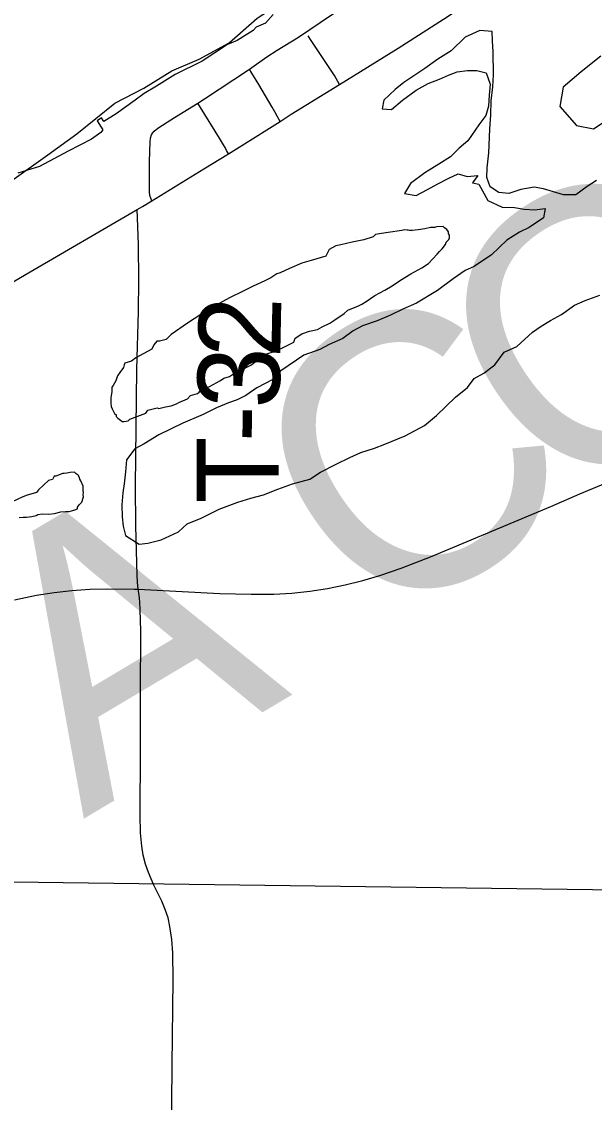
# Model space of a CAD drawing. Extents: x 63.4 to 97.4, y 0.4 to 22.4.
# Drawn here: x 66.101 to 66.497, y 16.424 to 17.173 of the extents above; entities that cross this region are included whole.
import ezdxf

# ---------------------------------------------------------------- set-up
doc = ezdxf.new("R2010")
doc.units = 0
for name, color, linetype in [('GM_X_County_Road', 7, 'Continuous'), ('GM_X_County_Text', 7, 'Continuous'), ('GM_X_Major_Lake', 7, 'Continuous'), ('GM_X_Minor_River', 7, 'Continuous'), ('GM_X_Section', 7, 'Continuous'), ('GM_X_State_Route', 7, 'Continuous'), ('GM_X_Township_Road', 7, 'Continuous'), ('GM_X_Township_Road_Text', 7, 'Continuous'), ('SH_Cut_Line', 7, 'Continuous')]:
    doc.layers.add(name, color=color, linetype=linetype)

msp = doc.modelspace()

# ---------------------------------------------------------------- linework, layer by layer
at = {"layer": 'GM_X_County_Road'}
msp.add_lwpolyline([(66.27518, 17.17769), (66.26982, 17.17168), (66.26348, 17.16907), (66.2612, 17.16664), (66.25015, 17.15981), (66.24348, 17.15688), (66.22593, 17.1455), (66.2074, 17.13624), (66.1944, 17.12811), (66.18595, 17.12307), (66.17961, 17.11852), (66.16644, 17.10893), (66.158, 17.10375), (66.15634, 17.10613), (66.15344, 17.10406), (66.15718, 17.09788), (66.15588, 17.09593), (66.14937, 17.09138), (66.13328, 17.08309), (66.11345, 17.07252), (66.09849, 17.06781)], dxfattribs=at)
at = {"layer": 'GM_X_Major_Lake'}
for points in [[(66.11926, 17.08066), (66.13935, 17.0951), (66.16551, 17.11638), (66.18561, 17.12664), (66.20495, 17.1388), (66.22391, 17.14677), (66.24476, 17.15817), (66.2641, 17.17527), (66.28306, 17.18743), (66.30163, 17.20642), (66.32097, 17.21972), (66.34182, 17.23834), (66.36268, 17.24935), (66.38429, 17.26265), (66.40325, 17.27937), (66.42524, 17.29419), (66.44685, 17.30786), (66.46619, 17.32192), (66.48515, 17.33674), (66.50638, 17.35497)], [(66.09423, 17.06281), (66.11926, 17.08066)]]:
    msp.add_lwpolyline(points, dxfattribs=at)
at = {"layer": 'GM_X_Minor_River'}
for points in [[(66.49891, 17.0629), (66.49248, 17.05869), (66.48454, 17.05295), (66.47618, 17.05291), (66.46212, 17.05703), (66.45566, 17.05814), (66.44655, 17.05658), (66.43821, 17.05387), (66.43137, 17.0546), (66.42528, 17.05838), (66.42297, 17.06483), (66.42331, 17.07167), (66.4244, 17.08194), (66.42508, 17.09829), (66.42579, 17.10817), (66.42612, 17.11805), (66.42721, 17.12756), (66.42754, 17.13593), (66.42746, 17.15189), (66.42704, 17.15949), (66.42663, 17.16595), (66.41827, 17.16667), (66.40805, 17.16206), (66.39822, 17.15251), (66.38914, 17.14677), (66.38006, 17.14026), (66.36568, 17.1307), (66.35963, 17.12573), (66.3517, 17.11847), (66.35059, 17.11238), (66.35705, 17.11203), (66.36461, 17.11853), (66.37406, 17.12541), (66.38239, 17.13001), (66.39035, 17.13309), (66.39641, 17.13578), (66.40247, 17.13809), (66.40968, 17.13888), (66.41614, 17.13891), (66.4226, 17.13742), (66.4253, 17.12945), (66.42459, 17.12187), (66.42424, 17.11424), (66.42237, 17.10777), (66.41747, 17.10129), (66.40993, 17.09023), (66.40388, 17.08526), (66.39784, 17.07915), (66.38989, 17.07418), (66.38005, 17.06805), (66.37022, 17.06078), (66.36607, 17.05392), (66.37406, 17.05244), (66.38201, 17.05665), (66.3892, 17.06049), (66.39677, 17.06432), (66.40321, 17.0674), (66.4093, 17.06552), (66.41689, 17.06632), (66.413, 17.0611), (66.41745, 17.06028), (66.42381, 17.04887), (66.4337, 17.04435), (66.44206, 17.04401), (66.4489, 17.0429), (66.45611, 17.04256), (66.46332, 17.04335), (66.46222, 17.03688), (66.45238, 17.03037), (66.44556, 17.02692), (66.43686, 17.02156), (66.42628, 17.01125), (66.41417, 17.00321), (66.40811, 17.00052), (66.39979, 16.99478), (66.38882, 16.98675), (66.37443, 16.97794), (66.36496, 16.97371), (66.35625, 16.96949), (66.34716, 16.96565), (66.33693, 16.96218), (66.33049, 16.95873), (66.32331, 16.95337), (66.31383, 16.94915), (66.3074, 16.9457), (66.29641, 16.94185), (66.28051, 16.93113), (66.27485, 16.92502), (66.26387, 16.91927), (66.2563, 16.91391), (66.25024, 16.91084), (66.24418, 16.90892), (66.23584, 16.90546), (66.22676, 16.90085), (66.21274, 16.89471), (66.19607, 16.88665)], [(66.50189, 17.14882), (66.48828, 17.13811), (66.47581, 17.12741), (66.47359, 17.1141), (66.48505, 17.10085), (66.49683, 17.09862), (66.50819, 17.1059)], [(66.50189, 17.14882), (66.48828, 17.13811), (66.47581, 17.12741), (66.47359, 17.1141), (66.48505, 17.10085), (66.49683, 17.09862), (66.50819, 17.1059)], [(66.37143, 17.02819), (66.36609, 17.02861), (66.36418, 17.02825), (66.35468, 17.0268), (66.35011, 17.02608), (66.34745, 17.02571), (66.34593, 17.02535), (66.3444, 17.02384), (66.33793, 17.02161), (66.32994, 17.02015), (66.32195, 17.01831), (66.31852, 17.01758), (66.31395, 17.01495), (66.31163, 17.01041), (66.30136, 17.00745), (66.29488, 17.0056), (66.2865, 17.00187), (66.28002, 16.99888), (66.27774, 16.99814), (66.27354, 16.99551), (66.26934, 16.99326), (66.26134, 16.98953), (66.25448, 16.98616), (66.24495, 16.98167), (66.23579, 16.97643), (66.22511, 16.97005), (66.21595, 16.96404), (66.20449, 16.95616), (66.20105, 16.95276), (66.19648, 16.95166), (66.19459, 16.95167), (66.19266, 16.94903), (66.19112, 16.946), (66.18006, 16.94001), (66.17701, 16.93775), (66.17244, 16.93627), (66.17205, 16.93513), (66.17166, 16.93323), (66.16897, 16.92984), (66.16744, 16.92757), (66.16627, 16.92416), (66.16434, 16.92076), (66.16358, 16.91962), (66.16355, 16.91659), (66.16315, 16.91393), (66.16276, 16.91204), (66.16273, 16.90862), (66.1631, 16.90634), (66.16384, 16.90481), (66.16421, 16.90367), (66.16534, 16.90139), (66.16647, 16.90062), (66.16646, 16.89948), (66.16759, 16.89833), (66.16948, 16.8968), (66.17061, 16.89603), (66.17213, 16.89602), (66.17479, 16.89638), (66.17594, 16.89751), (66.18699, 16.9016), (66.18852, 16.90387), (66.19499, 16.90534), (66.19613, 16.90495), (66.2007, 16.90606), (66.2045, 16.90679), (66.20831, 16.90828), (66.20984, 16.90903), (66.21593, 16.91164), (66.21785, 16.9139), (66.2228, 16.91538), (66.22394, 16.91614), (66.22509, 16.91765), (66.23119, 16.92026), (66.23881, 16.92438), (66.24111, 16.92588), (66.24491, 16.92699), (66.24759, 16.92887), (66.25178, 16.93112), (66.25979, 16.93485), (66.26934, 16.94238), (66.27733, 16.94498), (66.28305, 16.94759), (66.28801, 16.95021), (66.28953, 16.95096), (66.29031, 16.95361), (66.29489, 16.95662), (66.30022, 16.95848), (66.30593, 16.95957), (66.30898, 16.96145), (66.31432, 16.96407), (66.31776, 16.96632), (66.32425, 16.97083), (66.32692, 16.97309), (66.33416, 16.97607), (66.33645, 16.97719), (66.3395, 16.97907), (66.34561, 16.9832), (66.35248, 16.98694), (66.35744, 16.98994), (66.36316, 16.9937), (66.37041, 16.9982)], [(66.37125, 17.02792), (66.36609, 17.02861), (66.36418, 17.02825), (66.35468, 17.0268), (66.35011, 17.02608), (66.34745, 17.02571), (66.34593, 17.02535), (66.3444, 17.02384), (66.33793, 17.02161), (66.32994, 17.02015), (66.32195, 17.01831), (66.31852, 17.01758), (66.31395, 17.01495), (66.31163, 17.01041), (66.30136, 17.00745), (66.29488, 17.0056), (66.2865, 17.00187), (66.28002, 16.99888), (66.27774, 16.99814), (66.27354, 16.99551), (66.26934, 16.99326), (66.26134, 16.98953), (66.25448, 16.98616), (66.24495, 16.98167), (66.23579, 16.97643), (66.22511, 16.97005), (66.21595, 16.96404), (66.20449, 16.95616), (66.20105, 16.95276), (66.19648, 16.95166), (66.19459, 16.95167), (66.19266, 16.94903), (66.19112, 16.946), (66.18006, 16.94001), (66.17701, 16.93775), (66.17244, 16.93627), (66.17205, 16.93513), (66.17166, 16.93323), (66.16897, 16.92984), (66.16744, 16.92757), (66.16627, 16.92416), (66.16434, 16.92076), (66.16358, 16.91962), (66.16355, 16.91659), (66.16315, 16.91393), (66.16276, 16.91204), (66.16273, 16.90862), (66.1631, 16.90634), (66.16384, 16.90481), (66.16421, 16.90367), (66.16534, 16.90139), (66.16647, 16.90062), (66.16646, 16.89948), (66.16759, 16.89833), (66.16948, 16.8968), (66.17061, 16.89603), (66.17213, 16.89602), (66.17479, 16.89638), (66.17594, 16.89751), (66.18699, 16.9016), (66.18852, 16.90387), (66.19499, 16.90534), (66.19613, 16.90495), (66.2007, 16.90606), (66.2045, 16.90679), (66.20831, 16.90828), (66.20984, 16.90903), (66.21593, 16.91164), (66.21785, 16.9139), (66.2228, 16.91538), (66.22394, 16.91614), (66.22509, 16.91765), (66.23119, 16.92026), (66.23881, 16.92438), (66.24111, 16.92588), (66.24491, 16.92699), (66.24759, 16.92887), (66.25178, 16.93112), (66.25979, 16.93485), (66.26934, 16.94238), (66.27733, 16.94498), (66.28305, 16.94759), (66.28801, 16.95021), (66.28953, 16.95096), (66.29031, 16.95361), (66.29489, 16.95662), (66.30022, 16.95848), (66.30593, 16.95957), (66.30898, 16.96145), (66.31432, 16.96407), (66.31776, 16.96632), (66.32425, 16.97083), (66.32692, 16.97309), (66.33416, 16.97607), (66.33645, 16.97719), (66.3395, 16.97907), (66.34561, 16.9832), (66.35248, 16.98694), (66.35744, 16.98994), (66.36316, 16.9937), (66.37041, 16.9982)], [(66.37041, 16.9982), (66.37804, 17.00232), (66.38262, 17.00533), (66.38875, 17.01173), (66.39028, 17.01362), (66.39219, 17.01551), (66.39449, 17.01853), (66.39489, 17.02004), (66.3968, 17.02193), (66.39719, 17.02306), (66.3972, 17.02496), (66.39645, 17.02611), (66.39646, 17.02725), (66.39533, 17.02877), (66.39382, 17.02992), (66.39269, 17.03107), (66.38813, 17.03073), (66.38699, 17.03036), (66.38395, 17.03038), (66.38014, 17.02927), (66.37558, 17.02854), (66.37143, 17.02819)], [(66.33262, 17.02348), (66.33262, 17.02355)], [(66.19607, 16.88665), (66.18585, 16.88052), (66.17942, 16.87706), (66.17376, 16.86944), (66.17304, 16.86107), (66.17195, 16.85271), (66.17122, 16.84662), (66.1705, 16.83825), (66.17055, 16.82989), (66.17134, 16.82344), (66.17289, 16.81698), (66.18241, 16.81094), (66.18848, 16.81173), (66.19758, 16.81405), (66.2097, 16.81943), (66.21575, 16.82516), (66.22522, 16.82901), (66.23772, 16.83515), (66.2506, 16.84015), (66.2597, 16.84285), (66.26842, 16.84517), (66.27827, 16.84902), (66.28851, 16.85287), (66.30064, 16.85597), (66.30783, 16.86094), (66.31881, 16.86631), (66.32828, 16.87092), (66.33586, 16.87437), (66.34533, 16.87746), (66.35253, 16.88016), (66.36655, 16.88592), (66.3798, 16.89321), (66.38812, 16.90009), (66.40134, 16.91269), (66.40966, 16.91957), (66.41419, 16.92567), (66.421, 16.92951), (66.42856, 16.93524), (66.43497, 16.94401), (66.44369, 16.94786), (66.45465, 16.95779), (66.4607, 16.962), (66.46713, 16.96583), (66.47471, 16.97005), (66.48379, 16.97655), (66.49098, 16.97962), (66.50122, 16.98347)], [(66.14029, 16.85866), (66.13877, 16.85981), (66.13764, 16.86096), (66.1346, 16.86061), (66.13232, 16.86024), (66.13042, 16.85988), (66.12928, 16.85989), (66.12661, 16.85877), (66.12471, 16.85802), (66.12357, 16.85803), (66.12241, 16.85576), (66.11975, 16.85502)], [(66.11975, 16.85502), (66.11286, 16.84862), (66.11133, 16.84673), (66.10752, 16.84562), (66.10486, 16.84488), (66.10181, 16.84376), (66.09419, 16.84002)], [(66.09942, 16.82935), (66.10209, 16.82971), (66.10436, 16.82969), (66.10816, 16.83005), (66.11121, 16.83078), (66.11235, 16.83153), (66.11577, 16.83189), (66.11995, 16.83186), (66.12375, 16.83221), (66.12832, 16.83331), (66.13136, 16.83367), (66.13402, 16.83365), (66.13554, 16.83402), (66.13783, 16.83476), (66.13973, 16.83551), (66.13974, 16.83665), (66.14089, 16.83816), (66.1428, 16.84004), (66.14397, 16.84383), (66.1436, 16.84535), (66.14399, 16.84687), (66.14362, 16.84801), (66.14365, 16.85105), (66.14216, 16.85485), (66.14141, 16.856), (66.14103, 16.85714), (66.14029, 16.85866)]]:
    msp.add_lwpolyline(points, dxfattribs=at)
at = {"layer": 'GM_X_Section'}
msp.add_lwpolyline([(66.68776, 16.56928), (66.716, 16.56874), (66.70719, 15.57748), (66.70364, 15.57723), (65.68816, 15.5852), (65.69377, 16.5825)], close=True, dxfattribs=at)
at = {"layer": 'GM_X_State_Route'}
msp.add_lwpolyline([(66.09617, 16.77234), (66.1113, 16.77566), (66.12353, 16.7776), (66.13585, 16.77897), (66.14821, 16.77985), (66.1606, 16.78013), (66.17922, 16.77982), (66.18182, 16.77973), (66.23821, 16.77694), (66.26, 16.77629), (66.27557, 16.77645), (66.28803, 16.77714), (66.30045, 16.77842), (66.31279, 16.78029), (66.32502, 16.78276), (66.33712, 16.7858), (66.34908, 16.78936), (66.36382, 16.79443), (66.38413, 16.80231), (66.46733, 16.83708), (66.48731, 16.84575), (66.5418, 16.86847)], dxfattribs=at)
at = {"layer": 'GM_X_Township_Road'}
for points in [[(66.25869, 17.13987), (66.27082, 17.14852), (66.2779, 17.15316), (66.29273, 17.16202), (66.31556, 17.17741), (66.33122, 17.18732), (66.35945, 17.20611), (66.37561, 17.21671)], [(66.32108, 17.12929), (66.3616, 17.15452), (66.39306, 17.17449), (66.39973, 17.17898)], [(66.32108, 17.12929), (66.31761, 17.13543), (66.30108, 17.16046), (66.29949, 17.16304)], [(66.22292, 17.11641), (66.22762, 17.11934), (66.25806, 17.13943), (66.25869, 17.13987)], [(66.27991, 17.10377), (66.27787, 17.10741), (66.27626, 17.11034), (66.2744, 17.11368), (66.26514, 17.12933), (66.26032, 17.1372), (66.25869, 17.13987)], [(66.27991, 17.10377), (66.28768, 17.10869), (66.32108, 17.12929)], [(66.19109, 17.04875), (66.19043, 17.05051), (66.18992, 17.05242), (66.1896, 17.05505), (66.18962, 17.07573), (66.18999, 17.0898), (66.19028, 17.09214), (66.19087, 17.09434), (66.19167, 17.09567), (66.19285, 17.09698), (66.19409, 17.09823), (66.19597, 17.09953), (66.2069, 17.10643), (66.22292, 17.11641)], [(66.24413, 17.08125), (66.24293, 17.08353), (66.24186, 17.08566), (66.24082, 17.0875), (66.23801, 17.09205), (66.22478, 17.11341), (66.22292, 17.11641)], [(66.24413, 17.08125), (66.25357, 17.08706), (66.27991, 17.10377)], [(66.19109, 17.04875), (66.22713, 17.07078), (66.24413, 17.08125)], [(66.18101, 17.04274), (66.1847, 17.0449), (66.19109, 17.04875)], [(65.59259, 16.74035), (65.59502, 16.74133), (65.62337, 16.75324), (65.64882, 16.76471), (65.66548, 16.77301), (65.70117, 16.79192), (65.71801, 16.79998), (65.74624, 16.81297), (65.77193, 16.82404), (65.8092, 16.83953), (65.8291, 16.84824), (65.84308, 16.85488), (65.85959, 16.86344), (65.90882, 16.88996), (65.94996, 16.91189), (65.99959, 16.93762), (66.02131, 16.94965), (66.05337, 16.96811), (66.10431, 16.99791), (66.18101, 17.04274)], [(66.18182, 16.77973), (66.18129, 16.78458), (66.18106, 16.78958), (66.18015, 16.82361), (66.17991, 16.85146), (66.18083, 16.93189), (66.18185, 16.9721), (66.1823, 16.9937), (66.1819, 17.01836), (66.18123, 17.03689), (66.18101, 17.04274)], [(66.20473, 16.39741), (66.20529, 16.45025), (66.20593, 16.50932), (66.20564, 16.52793), (66.20499, 16.53717), (66.20376, 16.54634), (66.20241, 16.55232), (66.20051, 16.55813), (66.19807, 16.56376), (66.19258, 16.57493), (66.18892, 16.58358), (66.18686, 16.5895), (66.18528, 16.5956), (66.18423, 16.6018), (66.18339, 16.61116), (66.18303, 16.62364), (66.18333, 16.66717), (66.18335, 16.7076), (66.18347, 16.7511), (66.1832, 16.76555), (66.18287, 16.77106), (66.18241, 16.77572), (66.18182, 16.77973)]]:
    msp.add_lwpolyline(points, dxfattribs=at)
at = {"layer": 'SH_Cut_Line'}
msp.add_lwpolyline([(66.27518, 17.17769), (66.26982, 17.17168), (66.26348, 17.16907), (66.2612, 17.16664), (66.25015, 17.15981), (66.24348, 17.15688), (66.22593, 17.1455), (66.2074, 17.13624), (66.1944, 17.12811), (66.18595, 17.12307), (66.17961, 17.11852), (66.16644, 17.10893), (66.158, 17.10375), (66.15634, 17.10613), (66.15344, 17.10406), (66.15718, 17.09788), (66.15588, 17.09593), (66.14937, 17.09138), (66.13328, 17.08309), (66.11345, 17.07252), (66.09849, 17.06781)], dxfattribs=at)

# ---------------------------------------------------------------- texts
at = {"layer": 'GM_X_County_Text'}
for s, rotation, p in [('O', 33.92048, (66.47342, 16.82969)), ('C', 33.76964, (66.34481, 16.7437)), ('A', 30.78292, (66.14373, 16.62066))]:
    msp.add_text(s, height=0.18939, rotation=rotation, dxfattribs=at).set_placement(p)
at = {"layer": 'GM_X_Township_Road_Text'}
for s, rotation, p in [('2', 88.84466, (66.28002, 16.93961)), ('3', 88.88628, (66.27934, 16.90463)), ('-', 89.0086, (66.27894, 16.88133)), ('T', 90.02144, (66.27895, 16.83909))]:
    msp.add_text(s, height=0.05682, rotation=rotation, dxfattribs=at).set_placement(p)

doc.saveas('drawing.dxf')
